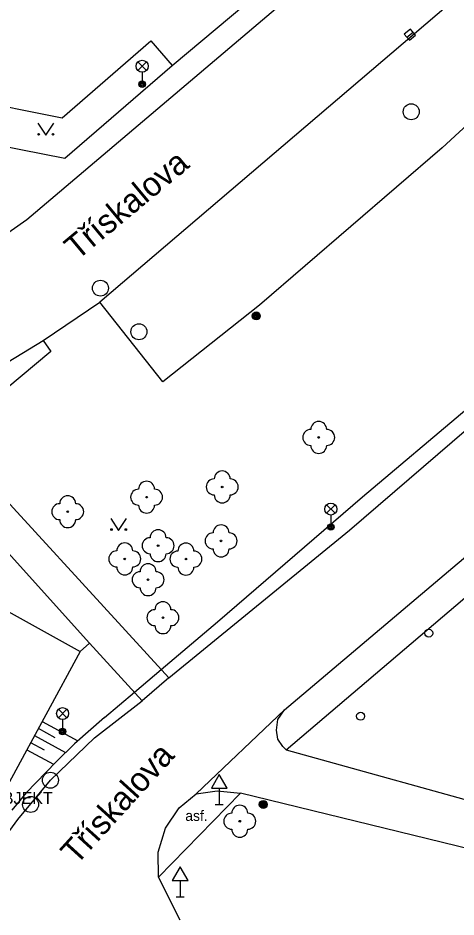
# Model space of a CAD drawing. Extents: x -598233 to -596890, y -1157848 to -1156431.
# Drawn here: x -597030.8 to -597003.4, y -1157692.2 to -1157635.8 of the extents above; entities that cross this region are included whole.
import ezdxf

# ---------------------------------------------------------------- set-up
doc = ezdxf.new("R2010")
doc.units = 0
for name, color, linetype in [('Level 10', 7, 'Continuous'), ('Level 11', 7, 'Continuous'), ('Level 14', 7, 'Continuous'), ('Level 15', 7, 'Continuous'), ('Level 22', 7, 'Continuous'), ('Level 25', 7, 'Continuous'), ('Level 27', 7, 'Continuous'), ('Level 28', 7, 'Continuous'), ('Level 33', 7, 'Continuous'), ('Level 34', 7, 'Continuous'), ('Level 36', 7, 'Continuous'), ('Level 40', 7, 'Continuous'), ('Level 41', 7, 'Continuous'), ('Level 5', 7, 'Continuous'), ('Level 50', 7, 'Continuous'), ('Level 7', 7, 'Continuous'), ('Level 9', 7, 'Continuous')]:
    doc.layers.add(name, color=color, linetype=linetype)

msp = doc.modelspace()

# ---------------------------------------------------------------- linework, layer by layer
at = {"layer": 'Level 10'}
for points in [[(-596966.61, -1157603.2), (-596962.68, -1157607.7199), (-596994.43, -1157634.9), (-597004.28, -1157643.98)], [(-597021.37, -1157677.18), (-597010.08, -1157667.93), (-596990.6599, -1157651.21), (-596982.85, -1157644.48), (-596935.69, -1157604.9699)], [(-597014.15, -1157679.18), (-596977.54, -1157648.21), (-596930.17, -1157607.85)], [(-597044.81, -1157654.08), (-597042.24, -1157654.04), (-597039.73, -1157653.71), (-597036.2, -1157652.12), (-597032.81, -1157650.25), (-597030.26, -1157648.4699), (-596998.03, -1157621.12)], [(-597004.28, -1157643.98), (-597015.71, -1157653.84)], [(-597029.25, -1157656.04), (-597025.7, -1157653.65)], [(-597015.71, -1157653.84), (-597021.75, -1157658.64), (-597025.7, -1157653.65)], [(-597038.4099, -1157661.63), (-597029.25, -1157656.04)], [(-597021.37, -1157677.18), (-597023.05, -1157678.61)], [(-597026.04, -1157680.94), (-597023.05, -1157678.61)], [(-597014.03, -1157681.69), (-597014.24, -1157681.48), (-597014.55, -1157681.02), (-597014.65, -1157680.46), (-597014.55, -1157679.78), (-597014.15, -1157679.18)], [(-597034.14, -1157691.17), (-597032.58, -1157688.43), (-597030.83, -1157686.06), (-597028.79, -1157683.59), (-597026.04, -1157680.94)], [(-597014.03, -1157681.69), (-596999.92, -1157685.61)], [(-597019.6599, -1157684.44), (-597018.35, -1157684.26), (-597016.9, -1157684.4099)], [(-597022.04, -1157688.1), (-597021.58, -1157686.6), (-597020.73, -1157685.33), (-597019.6599, -1157684.44)], [(-597000.67, -1157688.36), (-597016.9, -1157684.4099)], [(-597020.68, -1157692.36), (-597022.02, -1157689.67), (-597022.04, -1157688.1)]]:
    msp.add_lwpolyline(points, dxfattribs=at)
at = {"layer": 'Level 11'}
for points in [[(-596966.61, -1157603.2), (-597025.7, -1157653.65)], [(-597025.4, -1157679.67), (-597023.53, -1157678.08), (-597021.85, -1157676.66), (-597018.33, -1157673.67), (-597009.26, -1157665.83), (-596996.2, -1157654.82), (-596996.35, -1157654.94), (-596989.44, -1157649.12), (-596966.11, -1157629.32)], [(-597021.17, -1157638.83), (-597015.67, -1157634.18)], [(-597034.4099, -1157640.83), (-597034.11, -1157640.89), (-597028.05, -1157642.1), (-597022.5, -1157637.28), (-597021.17, -1157638.83)], [(-597027.89, -1157644.63), (-597021.17, -1157638.83)], [(-597034.9, -1157643.25), (-597027.89, -1157644.63)], [(-597014.03, -1157681.69), (-596983.01, -1157655.27), (-596976.4699, -1157649.7)], [(-597029.25, -1157656.04), (-597028.77, -1157656.74), (-597035.2, -1157662.1), (-597021.37, -1157677.18)], [(-597026.34, -1157675), (-597023.05, -1157678.61)], [(-597019.6599, -1157684.44), (-597014.15, -1157679.18)], [(-597022.02, -1157689.67), (-597016.9, -1157684.41)]]:
    msp.add_lwpolyline(points, dxfattribs=at)
at = {"layer": 'Level 14'}
for points in [[(-597025.4, -1157679.67), (-597027.29, -1157681.32)], [(-597027.29, -1157681.32), (-597028.44, -1157682.43)], [(-597028.44, -1157682.43), (-597030.3, -1157684.38)], [(-597030.3, -1157684.38), (-597031.2, -1157685.46)]]:
    msp.add_lwpolyline(points, dxfattribs=at)
at = {"layer": 'Level 15'}
for points in [[(-597028.5, -1157680.93), (-597029.54, -1157680.36)], [(-597029.3, -1157679.92), (-597027.08, -1157681.13)], [(-597029.78, -1157680.8), (-597027.84, -1157681.86)], [(-597029.1599, -1157681.71), (-597030.02, -1157681.24)], [(-597030.26, -1157681.68), (-597028.59, -1157682.59)]]:
    msp.add_lwpolyline(points, dxfattribs=at)
at = {"layer": 'Level 22'}
for centre in [(-597012, -1157662.12), (-597018.04, -1157665.2199), (-597022.77, -1157665.86), (-597027.71, -1157666.77), (-597018.11, -1157668.6), (-597022.05, -1157668.9), (-597024.14, -1157669.73), (-597020.31, -1157669.74), (-597022.68, -1157671.03), (-597021.75, -1157673.4099), (-597016.94, -1157686.1599)]:
    msp.add_circle(centre, 0.05, dxfattribs=at)
for centre, start, end in [((-597012, -1157661.62), 0, 180), ((-597012.5, -1157662.12), 90, 270), ((-597011.5, -1157662.12), 270, 90), ((-597012, -1157662.62), 180, 0), ((-597018.04, -1157664.7199), 0, 180), ((-597022.77, -1157665.36), 0, 180), ((-597018.54, -1157665.2199), 90, 270), ((-597017.54, -1157665.2199), 270, 90), ((-597023.27, -1157665.86), 90, 270), ((-597022.27, -1157665.86), 270, 90), ((-597018.04, -1157665.7199), 180, 0), ((-597028.21, -1157666.77), 90, 270), ((-597027.71, -1157666.27), 0, 180), ((-597027.21, -1157666.77), 270, 90), ((-597022.77, -1157666.36), 180, 0), ((-597027.71, -1157667.27), 180, 0), ((-597022.05, -1157668.4), 0, 180), ((-597018.11, -1157668.1), 0, 180), ((-597022.55, -1157668.9), 90, 270), ((-597021.55, -1157668.9), 270, 90), ((-597018.61, -1157668.6), 90, 270), ((-597017.61, -1157668.6), 270, 90), ((-597024.14, -1157669.23), 0, 180), ((-597020.31, -1157669.24), 0, 180), ((-597018.11, -1157669.1), 180, 0), ((-597024.64, -1157669.73), 90, 270), ((-597023.64, -1157669.73), 270, 90), ((-597022.05, -1157669.4), 180, 0), ((-597020.81, -1157669.74), 90, 270), ((-597019.81, -1157669.74), 270, 90), ((-597024.14, -1157670.23), 180, 0), ((-597022.68, -1157670.53), 0, 180), ((-597020.31, -1157670.24), 180, 0), ((-597023.18, -1157671.03), 90, 270), ((-597022.18, -1157671.03), 270, 90), ((-597022.68, -1157671.53), 180, 0), ((-597021.75, -1157672.9099), 0, 180), ((-597022.25, -1157673.4099), 90, 270), ((-597021.25, -1157673.4099), 270, 90), ((-597021.75, -1157673.9099), 180, 0), ((-597016.94, -1157685.6599), 0, 180), ((-597017.44, -1157686.1599), 90, 270), ((-597016.44, -1157686.1599), 270, 90), ((-597016.94, -1157686.6599), 180, 0)]:
    msp.add_arc(centre, 0.5, start, end, dxfattribs=at)
at = {"layer": 'Level 25'}
for centre, radius in [((-597015.9099, -1157654.51), 0.25), ((-597015.9099, -1157654.51), 0.2), ((-597015.9099, -1157654.51), 0.15), ((-597015.9099, -1157654.51), 0.1), ((-597015.9099, -1157654.51), 0.05), ((-597015.4699, -1157685.11), 0.25), ((-597015.4699, -1157685.11), 0.2), ((-597015.4699, -1157685.11), 0.15), ((-597015.4699, -1157685.11), 0.1), ((-597015.4699, -1157685.11), 0.05)]:
    msp.add_circle(centre, radius, dxfattribs=at)
at = {"layer": 'Level 27'}
msp.add_line((-597006.4816, -1157637.0506), (-597006.0984, -1157636.7294), dxfattribs=at)
msp.add_lwpolyline([(-597006.3209, -1157637.2422), (-597005.9378, -1157636.9209), (-597006.2591, -1157636.5378), (-597006.6422, -1157636.8591)], close=True, dxfattribs=at)
for centre in [(-597006.21, -1157641.7199), (-597025.6599, -1157652.77), (-597023.25, -1157655.5), (-597028.79, -1157683.59), (-597030.03, -1157685.11)]:
    msp.add_circle(centre, 0.5, dxfattribs=at)
at = {"layer": 'Level 28'}
for centre in [(-597005.11, -1157674.38), (-597009.38, -1157679.58)]:
    msp.add_circle(centre, 0.25, dxfattribs=at)
at = {"layer": 'Level 33'}
for p, q in [((-597023.315, -1157639.13), (-597022.785, -1157638.6)), ((-597023.315, -1157638.6), (-597022.785, -1157639.13)), ((-597023.05, -1157639.24), (-597023.05, -1157639.99)), ((-597011.505, -1157666.87), (-597010.975, -1157666.34)), ((-597011.505, -1157666.34), (-597010.975, -1157666.87)), ((-597011.24, -1157666.98), (-597011.24, -1157667.73)), ((-597028.295, -1157679.68), (-597027.765, -1157679.15)), ((-597028.295, -1157679.15), (-597027.765, -1157679.68)), ((-597028.03, -1157679.79), (-597028.03, -1157680.54))]:
    msp.add_line(p, q, dxfattribs=at)
for centre, radius in [((-597023.05, -1157638.865), 0.375), ((-597023.05, -1157639.99), 0.2), ((-597023.05, -1157639.99), 0.1445), ((-597023.05, -1157639.99), 0.0876), ((-597011.24, -1157666.605), 0.375), ((-597011.24, -1157667.73), 0.2), ((-597011.24, -1157667.73), 0.1445), ((-597011.24, -1157667.73), 0.0876), ((-597028.03, -1157679.415), 0.375), ((-597028.03, -1157680.54), 0.2), ((-597028.03, -1157680.54), 0.1445), ((-597028.03, -1157680.54), 0.0876)]:
    msp.add_circle(centre, radius, dxfattribs=at)
at = {"layer": 'Level 34'}
for p, q in [((-597018.2199, -1157684.092), (-597018.2199, -1157685.11)), ((-597018.4699, -1157685.11), (-597017.9699, -1157685.11)), ((-597020.67, -1157689.882), (-597020.67, -1157690.9)), ((-597020.92, -1157690.9), (-597020.42, -1157690.9))]:
    msp.add_line(p, q, dxfattribs=at)
for points in [[(-597018.7199, -1157684.092), (-597017.7199, -1157684.092), (-597018.2199, -1157683.226)], [(-597021.17, -1157689.882), (-597020.17, -1157689.882), (-597020.67, -1157689.016)]]:
    msp.add_lwpolyline(points, close=True, dxfattribs=at)
at = {"layer": 'Level 36'}
for points in [[(-597029.58, -1157642.43), (-597029.08, -1157643.18), (-597028.58, -1157642.43)], [(-597025.02, -1157667.19), (-597024.52, -1157667.94), (-597024.02, -1157667.19)]]:
    msp.add_lwpolyline(points, dxfattribs=at)
for centre in [(-597029.5302, -1157643.1298), (-597028.6308, -1157643.1298), (-597024.9702, -1157667.8898), (-597024.0708, -1157667.8898)]:
    msp.add_circle(centre, 0.05, dxfattribs=at)
at = {"layer": 'Level 5'}
for points in [[(-597032.21, -1157672.61), (-597026.92, -1157675.53)], [(-597026.92, -1157675.53), (-597035.54, -1157691.4)]]:
    msp.add_lwpolyline(points, dxfattribs=at)
at = {"layer": 'Level 7'}
for points in [[(-597038.4099, -1157661.63), (-597026.34, -1157675)], [(-597026.34, -1157675), (-597026.92, -1157675.53)]]:
    msp.add_lwpolyline(points, dxfattribs=at)
at = {"layer": 'Level 9'}
msp.add_lwpolyline([(-597026.34, -1157675), (-597023.05, -1157678.61)], dxfattribs=at)

# ---------------------------------------------------------------- texts
at = {"layer": 'Level 40'}
msp.add_text('asf.', height=0.65, dxfattribs=at).set_placement((-597020.35, -1157686.14))
at = {"layer": 'Level 41'}
msp.add_text('FIREMNÍ OBJEKT', height=0.75, dxfattribs=at).set_placement((-597036.95, -1157685.08))
at = {"layer": 'Level 50'}
for rotation, p in [(39.74657, (-597027.1155, -1157651.062)), (39.74657, (-597027.1155, -1157651.062)), (47.77284, (-597027.165, -1157688.9573)), (47.77284, (-597027.165, -1157688.9573))]:
    msp.add_text('Třískalova', height=1.5, rotation=rotation, dxfattribs=at).set_placement(p)

doc.saveas('drawing.dxf')
